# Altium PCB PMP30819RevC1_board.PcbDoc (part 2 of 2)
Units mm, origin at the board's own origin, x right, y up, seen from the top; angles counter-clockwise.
Board outline 73.66 x 66.04 mm, 4 copper layers (Top Layer, Layer 1, Layer 2, Bottom Layer), stack 1.787 mm thick; 100 components, 30 nets, 255 pads, 105 vias.
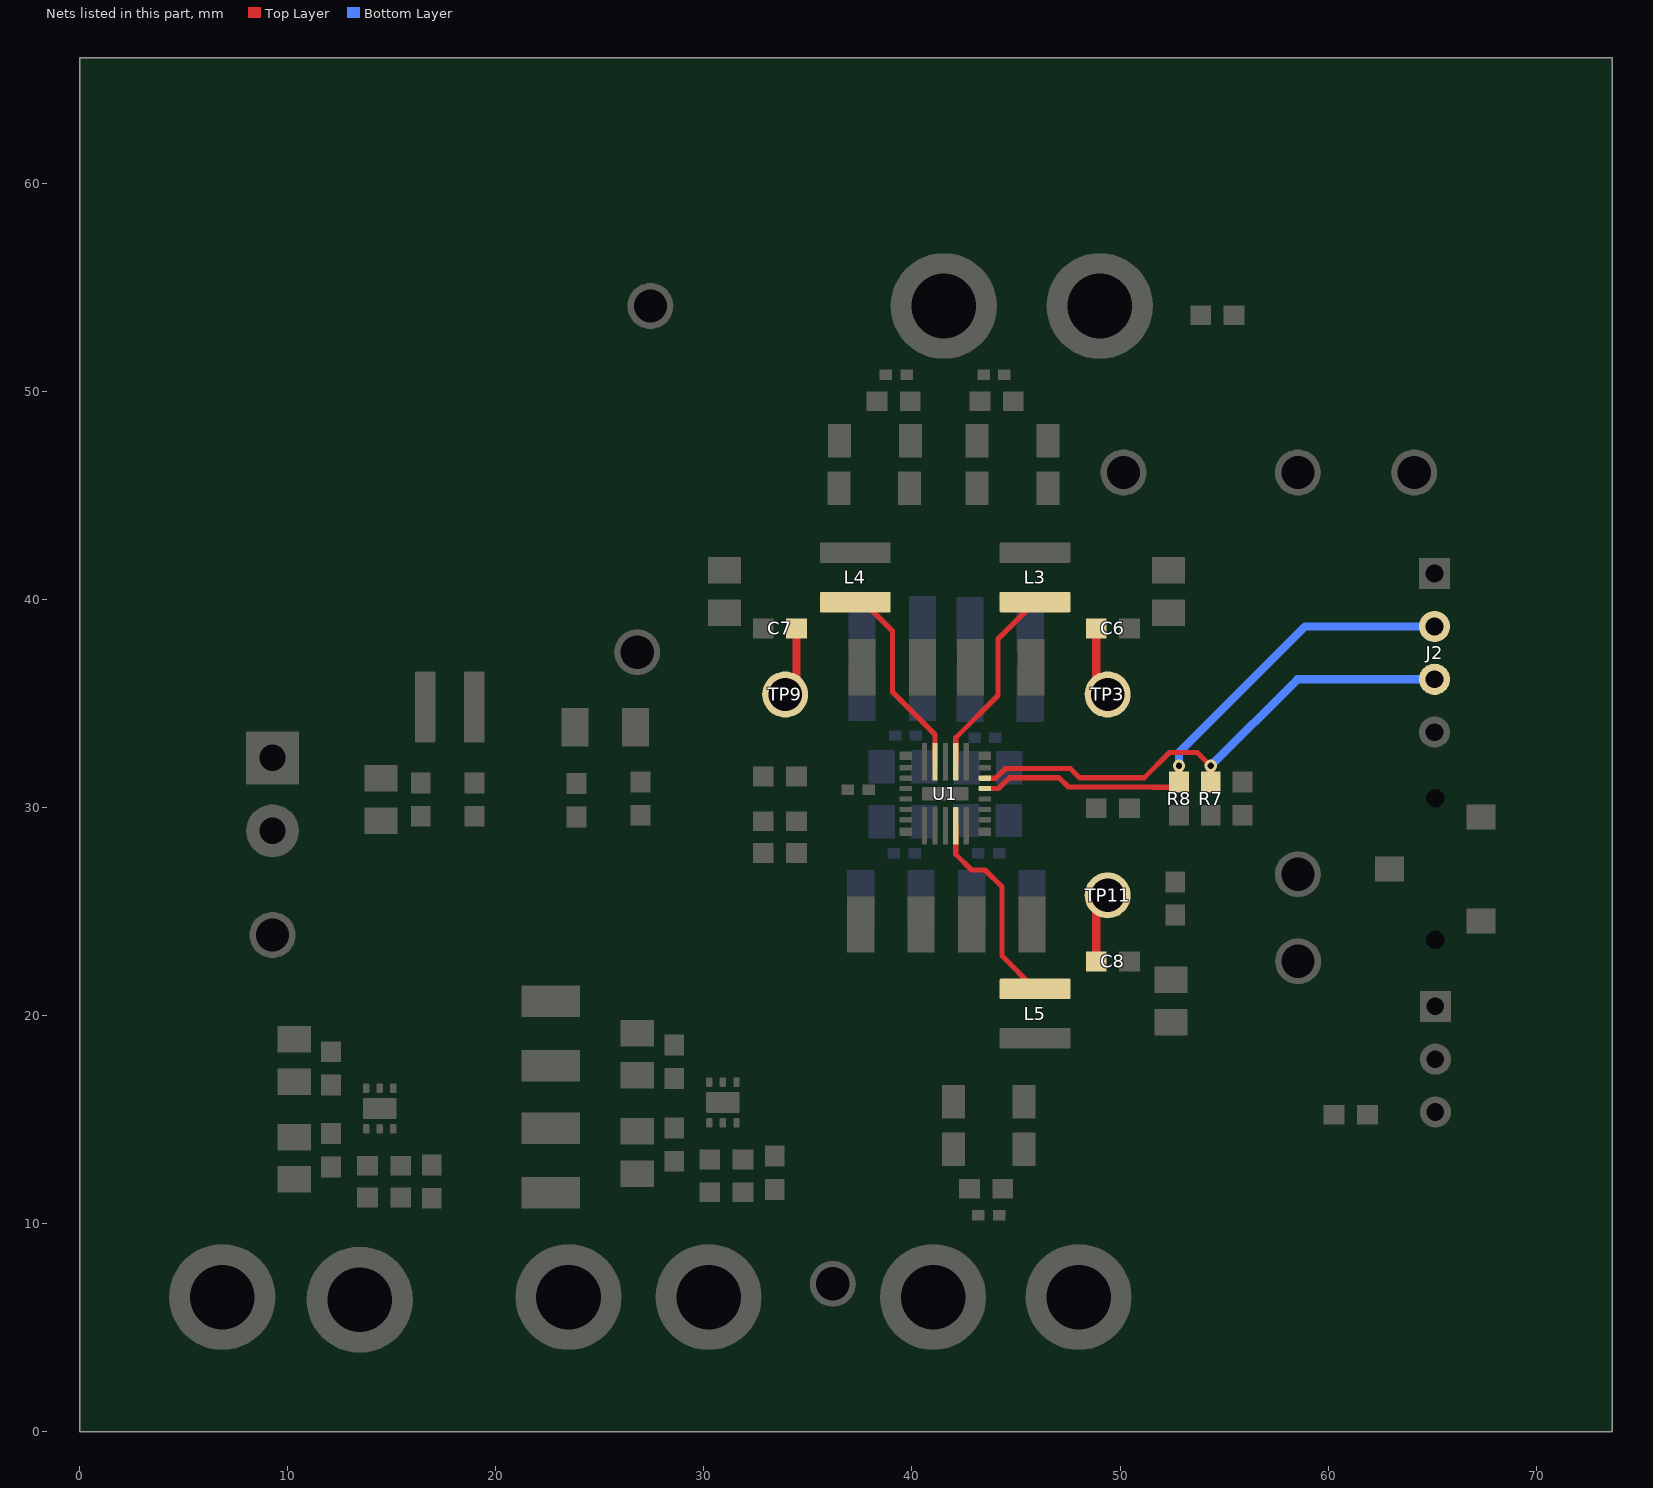
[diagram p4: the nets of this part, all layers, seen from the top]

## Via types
v1: diameter 0.6, hole 0.3, Top Layer to Bottom Layer, tented both sides, 66 vias
v2: diameter 0.7, hole 0.4, Top Layer to Bottom Layer, 20 vias
v3: diameter 0.6, hole 0.3, Top Layer to Bottom Layer, 11 vias
v4: diameter 0.9, hole 0.5, Top Layer to Bottom Layer, 6 vias
v5: diameter 0.9, hole 0.5, Top Layer to Bottom Layer, tented top, 1 vias
v6: diameter 0.7, hole 0.3, Top Layer to Bottom Layer, 1 vias

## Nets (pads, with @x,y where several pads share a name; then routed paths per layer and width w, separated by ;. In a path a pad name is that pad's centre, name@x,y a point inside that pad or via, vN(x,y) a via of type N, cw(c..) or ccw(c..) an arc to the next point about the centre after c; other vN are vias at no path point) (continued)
SCL: J2.2 R8.2 U1.5 | length 26
  Top Layer w0.25: U1.5@43.505,30.913 44.16,30.913 44.681,31.434 47.072,31.434 47.522,30.984 51.596,30.984 51.599,30.98 52.584,30.98 R8.2@52.832,31.228
  Top Layer w0.4: R8.2@52.832,31.228 v1(52.832,32.004)
  Bottom Layer w0.4: v1(52.832,32.004) 52.832,32.647 58.889,38.704 J2.2@65.113,38.704
SDA: J2.3 R7.2 U1.6 | length 25.3
  Top Layer w0.25: U1.6@43.505,31.413 44.024,31.413 44.495,31.884 47.259,31.884 47.265,31.877 47.607,31.877 48.051,31.434 51.158,31.434 52.376,32.651 53.709,32.651 v1(54.356,32.004)
  Top Layer w0.4: R7.2@54.356,31.228 v1(54.356,32.004)
  Bottom Layer w0.4: v1(54.356,32.004) 58.516,36.164 J2.3@65.113,36.164
SW_0: C6.1 L3.1 TP3.1 U1.10 | length 12.6
  Top Layer w0.25: U1.10@42.105,32.203 42.105,33.358 44.137,35.39 44.137,38.095 L3.1@45.915,39.873
  Top Layer w0.4: C6.1@48.857,38.608 48.857,35.979 TP3.1@49.403,35.433
SW_1: C7.1 L4.1 TP9.1 U1.12 | length 12.9
  Top Layer w0.25: L4.1@37.279,39.873 37.676,39.873 39.057,38.492 39.057,35.552 41.105,33.504 U1.12@41.105,32.203
  Top Layer w0.4: TP9.1@33.909,35.433 34.455,35.979 C7.1@34.455,38.608
SW_2: C8.1 L5.1 TP11.1 U1.25 | length 13.2
  Top Layer w0.25: U1.25@42.105,29.123 42.105,27.754 42.855,27.004 43.516,27.004 44.323,26.197 44.323,22.88 L5.1@45.915,21.288
  Top Layer w0.4: C8.1@48.857,22.606 48.857,25.235 TP11.1@49.403,25.781
pads on no net: S1.MH1 S1.MH2 U1. U1.23 U2.5 U2.7@13.973,15.537 U2.7@14.873,15.537 U12.5 U12.7@30.463,15.823 U12.7@31.363,15.823

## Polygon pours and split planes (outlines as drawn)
3V3 on Top Layer "TOP_LAYER_3V3_P000" (solid, remove dead copper, pour order 0): 23.989,10.776 20.683,10.776 20.263,11.196 20.263,11.75 20.739,12.227 23.989,12.227
GND on Top Layer "TOP_LAYER_GND_P152" (solid, remove dead copper, pour order 152): 2.286,23.876 31.936,23.876 38.645,17.167 38.645,5.014 41.119,2.54 59.711,2.54 59.711,63.5 2.54,63.5
3V3 on Top Layer "TOP_LAYER_3V3_P002" (solid, remove dead copper, pour order 2): 9.586,18.255 11.099,18.255 11.614,17.74 12.62,17.74 13.453,16.907 14.092,16.907 14.092,19.287 12.739,20.639 9.586,20.639
NetC34_1 on Top Layer "TOP_LAYER_NETC34_1_P004" (solid, remove dead copper, pour order 4): 9.5,12.776 11.136,12.776 11.614,13.254 13.373,13.25 13.373,13.601 13.614,13.843 13.896,13.843 14.322,13.417 14.322,10.317 15.114,9.525 16.637,8.001 16.637,2.54 10.311,2.54 10.311,10.481 9.521,11.27
NetC137_1 on Top Layer "TOP_LAYER_NETC137_1_P006" (solid, remove dead copper, pour order 6): 21.234,19.955 24.356,19.955 25.788,18.523 27.674,18.523 28.107,18.09 29.412,18.09 29.821,17.681 30.181,17.681 30.181,18.46 28.616,20.025 26.687,20.025 25.258,21.454 21.234,21.454
NetC134_1 on Top Layer "TOP_LAYER_NETC134_1_P012" (solid, remove dead copper, pour order 12): 30.003,14.001 29.562,13.56 29.382,13.56 29.307,13.485 27.958,13.485 27.529,13.056 26.01,13.056 26.01,11.666 26.372,11.303 26.372,10.218 27.608,8.983 27.608,2.573 32.732,2.573 32.732,7.9 30.813,9.819 30.813,13.655 30.462,14.005
GND on Top Layer "TOP_LAYER_GND_P150" (solid, remove dead copper, pour order 150): 17.4,8.08 14.579,10.9 9.573,10.9 9.573,2.54 2.466,2.54 2.466,23.013 26.233,23.013 37.421,23.013 39.535,20.899 39.559,9.525 26.338,9.525 26.338,2.54 17.4,2.54
GND on Top Layer "TOP_LAYER_GND_P144" (solid, remove dead copper, pour order 144): 43.472,21.717 43.472,20.282 44.069,19.685 43.479,19.095 43.479,5.358 41.989,3.867 40.172,3.867 38.481,5.559 38.481,22.208 40.022,23.749 42.623,23.749
NetC7_2 on Top Layer "TOP_LAYER_NETC7_2_P142" (solid, remove dead copper, pour order 142): 33.401,37.922 33.06,37.581 31.133,37.581 30.207,38.506 30.207,40.065 30.263,40.121 32.904,40.121 33.401,39.624
GND on Top Layer "TOP_LAYER_GND_P138" (solid, remove dead copper, pour order 138): 39.851,40.001 39.212,40.64 33.819,40.64 33.589,40.41 30.456,40.41 30.099,40.767 30.099,42.36 30.263,42.524 32.185,42.524 33.18,41.529 39.274,41.529 39.861,42.116
GND on Top Layer "TOP_LAYER_GND_P132" (solid, remove dead copper, pour order 132): 43.18,41.529 50.686,41.529 51.956,42.799 55.35,42.799 55.584,42.565 55.584,41.058 55.165,40.638 43.931,40.638 43.415,40.121 43.035,40.121
NetC6_2 on Top Layer "TOP_LAYER_NETC6_2_P126" (solid, remove dead copper, pour order 126): 49.936,39.333 50.679,40.076 53.049,40.076 53.34,39.785 53.34,37.867 52.768,37.295 50.317,37.295 49.936,37.676
NetC8_2 on Top Layer "TOP_LAYER_NETC8_2_P122" (solid, remove dead copper, pour order 122): 53.467,20.959 50.49,20.959 49.94,21.509 49.94,23.106 50.165,23.331 53.193,23.331 53.631,22.893 53.631,21.063 53.467,20.899
GND on Top Layer "TOP_LAYER_GND_P120" (solid, remove dead copper, pour order 120): 43.481,23.341 43.481,21.103 44.137,20.447 53.176,20.447 53.467,20.156 53.467,18.791 53.26,18.584 50.487,18.584 49.385,19.685 40.411,19.685 39.756,20.34 39.756,26.161 41.127,27.532 41.127,27.772 41.384,28.028 41.605,28.028 41.783,27.851 41.783,26.645 42.545,25.883 43.332,25.883 43.485,25.73
GND on Top Layer "TOP_LAYER_GND_P116" (solid, remove dead copper, pour order 116): 71.12,63.5 61.341,63.5 61.341,2.54 71.12,2.54
GND on Top Layer "TOP_LAYER_GND_P114" (solid, remove dead copper, pour order 114): 7.747,30.099 27.413,30.099 27.413,23.876 7.747,23.876
3V3 on Top Layer "TOP_LAYER_3V3_P112" (solid, remove dead copper, pour order 112): 49.107,19.431 44.207,19.431 43.815,19.039 43.815,9.157 46.495,6.477 48.26,6.477 49.107,7.324
5VS on Top Layer "TOP_LAYER_5VS_P108" (solid, remove dead copper, pour order 108): 29.464,49.27 29.464,49.216 29.972,48.708 29.972,42.816 29.781,42.625 29.781,38.257 31.563,36.475 31.563,23.876 28.107,23.876 28.107,30.48 26.037,30.48 26.036,30.663 26.036,47.565 27.74,49.27
NetC3_1 on Top Layer "TOP_LAYER_NETC3_1_P106" (solid, remove dead copper, pour order 106): 18.415,30.663 24.511,30.663 24.511,36.576 18.415,36.576
NetC1_1 on Top Layer "TOP_LAYER_NETC1_1_P104" (solid, remove dead copper, pour order 104): 7.747,30.734 17.116,30.734 17.116,36.576 7.747,36.576
1VD1 on Top Layer "TOP_LAYER_1VD1_P094" (solid, remove dead copper, pour order 94): 39.111,55.819 40.315,57.023 42.845,57.023 44.188,55.68 44.188,41.758 50.433,41.758 52.451,43.776 52.451,56.388 47.625,61.214 35.306,61.214 31.518,57.426 31.518,43.205 32.965,41.758 38.989,41.758 38.989,50.038 39.111,50.16
GND on Top Layer "TOP_LAYER_GND_P092" (solid, remove dead copper, pour order 92): 43.848,41.041 43.848,54.565 43.034,55.379 39.943,55.379 39.37,54.806 39.37,41.021
5VS on Top Layer "TOP_LAYER_5VS_P082" (solid, remove dead copper, pour order 82): 36.656,22.784 36.085,23.341 36.085,27.055 36.97,27.94 40.386,27.94 40.513,28.067 40.605,28.113 40.757,27.961 40.757,27.504 39.438,26.185 39.438,23.899 38.324,22.784
SW_2 on Top Layer "TOP_LAYER_SW_2_P080" (solid, remove dead copper, pour order 80): 42.123,26.647 cw(c42.462,26.987) 41.982,26.987 41.973,27.088 41.973,27.819 41.992,27.837 42.528,27.444 ccw(c43.171,28.087) 43.171,27.178 44.27,27.178 cw(c44.27,26.745) 44.577,27.051 44.608,27.02 cw(c44.091,26.483) 44.836,26.497 44.836,22.987 ccw(c45.17,22.98) 44.93,22.749 45.206,22.473 ccw(c45.747,23.029) 45.758,22.253 47.348,22.253 ccw(c47.348,22.784) 47.879,22.784 cw(c48.426,22.784) 48.426,23.331 49.187,23.331 cw(c49.188,22.934) 49.584,22.934 49.584,20.898 cw(c49.489,20.898) 49.489,20.803 48.978,20.803 44.45,20.803 44.094,20.803 cw(c44.094,21.082) 43.815,21.082 43.815,25.809 ccw(c43.427,25.809) 43.736,26.043 ccw(c43.364,25.671) 43.364,26.197 43.08,26.197 42.997,26.197 cw(c42.997,27.221) 42.273,26.497
5VS on Top Layer "TOP_LAYER_5VS_P062" (solid, remove dead copper, pour order 62): 42.926,27.94 46.183,27.94 47.072,27.051 47.072,23.183 46.673,22.784 45.288,22.784 45.083,22.989 45.083,26.968 44.588,27.463 43.488,27.463 43.138,27.813
5VS on Top Layer "TOP_LAYER_5VS_P058" (solid, remove dead copper, pour order 58): 45.036,38.09 46.822,38.09 47.312,37.6 47.312,34.203 46.319,33.21 43.737,33.21 43.63,33.317 45.036,34.724
5VS on Top Layer "TOP_LAYER_5VS_P050" (solid, remove dead copper, pour order 50): 39.705,33.363 37.085,33.363 36.095,34.352 36.095,37.478 36.754,38.137 38.295,38.137 38.295,35.078 39.692,33.681 39.692,33.565
SW_1 on Top Layer "TOP_LAYER_SW_1_P044" (solid, remove dead copper, pour order 44): 39.756,35.026 cw(c40.571,35.841) 39.418,35.841 39.429,35.902 39.429,39.826 ccw(c39.14,39.826) 39.345,40.03 39.08,40.295 ccw(c38.894,40.108) 38.894,40.372 34.7,40.372 ccw(c34.698,39.539) 33.865,39.54 33.865,38.308 ccw(c34.29,38.308) 34.29,37.883 35.244,37.883 ccw(c35.244,38.133) 35.42,37.956 cw(c36.347,37.03) 36.347,38.34 38.343,38.34 cw(c38.343,38.126) 38.557,38.126 38.557,35.548 ccw(c39.491,35.595) 38.864,34.901 40.017,33.748 40.861,33.748 41.015,33.87 40.911,33.87
GND on Top Layer "TOP_LAYER_GND_P042" (solid, remove dead copper, pour order 42): 43.848,40.515 43.848,41.566 39.355,41.566 39.355,40.379 39.819,39.915 39.819,35.406 41.127,34.098 41.884,34.098 41.884,34.12 42.03,34.12 43.434,35.524 43.434,40.101
SW_0 on Top Layer "TOP_LAYER_SW_0_P026" (solid, remove dead copper, pour order 26): 44.65,35.245 cw(c43.695,35.203) 44.401,34.558 43.724,33.881 cw(c43.485,34.12) 43.485,33.782 43.115,33.782 ccw(c43.115,32.834) 42.445,33.504 41.884,33.504 41.884,33.546 43.04,34.702 43.146,34.82 cw(c43.313,34.653) 43.313,34.889 ccw(c43.313,35.271) 43.583,35.001 43.718,35.136 ccw(c43.485,35.369) 43.815,35.369 43.815,40.048 cw(c44.103,40.048) 43.899,40.252 cw(c44.234,39.845) 44.234,40.372 48.856,40.372 cw(c48.856,39.801) 49.427,39.801 49.427,38.133 cw(c49.177,38.133) 49.177,37.883 48.605,37.883 cw(c48.605,38.227) 48.26,38.227 48.26,38.339 ccw(c48.073,38.339) 48.073,38.526 44.958,38.526 ccw(c44.958,38.233) 44.75,38.44 ccw(c45.004,38.187) 44.645,38.186 44.65,38.09
GND on Bottom Layer "BOTTOM_LAYER_GND_P098" (solid, remove dead copper, pour order 98): 71.12,2.54 71.12,63.5 2.54,63.5 2.54,2.54
5VS on Bottom Layer "BOTTOM_LAYER_5VS_P090" (solid, remove dead copper, pour order 90): 28.067,23.622 33.43,18.259 36.355,18.259 37.074,18.977 37.074,29.038 28.067,29.038
5VS on Bottom Layer "BOTTOM_LAYER_5VS_P086" (solid, remove dead copper, pour order 86): 26.036,40.076 32.206,40.076 36.085,43.955 36.085,47.401 34.255,49.231 27.702,49.231 26.036,47.565
5VS on Bottom Layer "BOTTOM_LAYER_5VS_P068" (solid, remove dead copper, pour order 68): 47.677,32.824 47.677,35.828 48.081,36.232 49.188,36.232 49.187,46.888 46.859,49.216 33.983,49.216 31.757,46.99 31.757,36.576 32.265,36.068 35.052,36.068 35.453,35.667 35.393,32.94 37.181,31.152 39.188,31.152 39.559,31.523 39.559,39.671 38.915,40.314 38.915,41.906 39.192,42.183 43.788,42.183 44.234,41.737 44.234,40.638 43.815,40.237 43.815,33.157 44.433,32.54 45.912,31.06
5VS on Bottom Layer "BOTTOM_LAYER_5VS_P066" (solid, remove dead copper, pour order 66): 47.677,27.929 47.677,25.258 48.051,24.884 49.149,24.884 49.149,18.706 47.677,17.234 34.445,17.234 31.8,19.879 31.8,23.959 36.382,28.541 38.896,28.541 39.37,28.067 39.37,22.823 39.645,22.548 43.587,22.548 43.801,22.762 43.801,28.436 47.117,28.489
5VS on Bottom Layer "BOTTOM_LAYER_5VS_P048" (solid, remove dead copper, pour order 48): 36.643,22.784 36.085,23.341 36.085,28.338 37.846,30.099 39.497,30.099 39.497,27.355 39.438,27.296 39.438,23.899 38.324,22.784
5VS on Bottom Layer "BOTTOM_LAYER_5VS_P046" (solid, remove dead copper, pour order 46): 43.861,30.226 45.974,30.226 47.117,29.083 47.117,23.228 46.673,22.784 45.288,22.784 45.083,22.989 45.083,26.655 44.484,27.254 44.297,27.254 43.861,27.69
GND on Bottom Layer "BOTTOM_LAYER_GND_P040" (solid, remove dead copper, pour order 40): 43.405,31.063 43.405,28.284 43.527,28.163 43.527,24.084 43.497,24.054 43.497,23.063 39.83,23.063 39.83,31.24
GND on Bottom Layer "BOTTOM_LAYER_GND_P024" (solid, remove dead copper, pour order 24): 43.375,30.263 43.375,34.065 43.43,34.12 43.43,40.137 43.931,40.638 43.931,41.566 39.25,41.566 39.25,40.484 39.819,39.915 39.819,30.263
5VS on Bottom Layer "BOTTOM_LAYER_5VS_P010" (solid, remove dead copper, pour order 10): 45.064,40.122 46.651,40.122 47.312,39.461 47.312,32.46 45.877,31.025 43.976,31.025 43.976,32.638 43.685,32.929 43.655,32.929 43.655,33.654 45.064,35.063
5VS on Bottom Layer "BOTTOM_LAYER_5VS_P008" (solid, remove dead copper, pour order 8): 39.188,32.651 39.559,33.022 39.559,33.779 39.409,33.929 39.409,34.027 38.299,35.137 38.299,40.181 36.428,40.181 36.099,39.852 36.099,32.234 37.181,31.152 39.188,31.152
GND on Layer 2 "LAYER_2_GND_P148" (solid, remove dead copper, pour order 148): 2.54,2.54 2.54,63.5 71.12,63.5 71.12,2.54
3V3 on Layer 2 "LAYER_2_3V3_P130" (solid, remove dead copper, pour order 130): 51.167,3.664 47.271,3.664 39.976,10.959 20.634,10.959 12.575,19.018 9.295,19.018 9.295,20.932 9.699,21.336 15,21.336 22.536,13.8 44.604,13.8 52.107,6.297 52.107,5.2
GND on Layer 1 "LAYER_1_GND_P146" (solid, remove dead copper, pour order 146): 71.12,2.54 71.12,63.5 2.54,63.5 2.54,2.54

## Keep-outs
Keep-Out Layer:
  text ".Layer_Name" at 14.656,-21.806 h1.52

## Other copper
Top Layer:
  pour cut-out: 8.073,23.174 8.128,22.871 8.52,22.479 8.647,22.352 9.751,22.352 9.878,22.479 10.343,22.943 10.343,23.114
  pour cut-out: 34.925,33.782 36.327,33.782 36.981,33.128 39.99,33.128 40.005,33.113 40.005,32.463 39.8,32.258 34.925,32.258
  text ".Layer_Name" at 14.656,-21.806 h1.52
Layer 1:
  pour cut-out: 44.069,21.844 44.069,20.701 47.752,20.701 47.752,21.844
  pour cut-out: 44.069,40.513 44.069,39.243 47.752,39.243 47.752,40.513
  pour cut-out: 35.433,40.513 35.433,39.114 39.116,39.114 39.116,40.513
  pour cut-out: 35.952,32.564 35.952,33.508 34.945,33.508 34.945,32.564
Layer 2:
  pour cut-out: 35.952,32.564 35.952,33.508 34.945,33.508 34.945,32.564
Bottom Layer:
  pour cut-out: 35.448,32.564 35.448,33.508 34.945,33.508 34.945,32.564
  text ".Layer_Name" at 14.656,-21.806 h1.52

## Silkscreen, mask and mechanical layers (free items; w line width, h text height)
Top Overlay:
  text "GND" at 40.124,57.426 h1
  text "1.1V" at 47.745,57.426 h1
  text "NWA" at 57.176,48.575 h1
  text "AGND" at 62.569,48.574 h1
  text "VIN" at 4.191,31.981 h1 r90
  text "GND" at 4.191,27.135 h1 r90
  text "NWA" at 56.475,24.689 h1 r90
  text "3v3" at 56.463,19.955 h1 r90
  text "'.PRJ_Number'.PCB_Rev" at 52.557,3.048 h2
  text "GND" at 5.461,2.032 h1
  text "2.5V" at 12.065,2.032 h1
  text "GND" at 21.869,2.032 h1
  text "1.1V" at 28.991,2.032 h1
  text "GND" at 39.83,2.032 h1
  text "3.3V" at 46.792,2.032 h1
  text ".Layer_Name" at 14.656,-21.806 h1.52
Bottom Overlay:
  text ".Layer_Name" at 14.656,-21.806 h1.52
Top Paste:
  text ".Layer_Name" at 14.656,-21.806 h1.52
Bottom Paste:
  text ".Layer_Name" at 14.656,-21.806 h1.52
Top Solder:
  text ".Layer_Name" at 14.656,-21.806 h1.52
  text ".Layer_Name" at 14.656,-21.806 h1.52
Bottom Solder:
  text "'.PRJ_Number'.PCB_Rev" at 70.358,3.529 h2
  text ".Layer_Name" at 14.656,-21.806 h1.52
Drill Guide:
  text ".Layer_Name" at 14.656,-21.806 h1.52
M1 Board Outline:
  the board outline again, w0.254
  text ".Layer_Name" at 14.656,-21.806 h1.52
M2 Board Dimensions:
  rectangle: 0,-6.985 3.175,-3.81
  rectangle: 3.175,-10.16 12.7,-6.985
  lines w0.178: 0,-6.985 25.4,-6.985 ; 3.175,-10.16 3.175,-3.81 ; 6.35,-10.16 6.35,-3.81 ; 12.7,-10.16 12.7,-3.81 ; 19.05,-10.16 19.05,-3.81 ; 0,-10.16 25.4,-10.16 25.4,-3.81 0,-3.81 0,-10.16
  text "'.Print_Date' '.Print_Time'" at 0.381,67.183 h1.5
  text ".Layer_Name" at 14.656,-21.806 h1.52
M3 3D STEP Top:
  text ".Layer_Name" at 14.656,-21.806 h1.52
M4 3D STEP Bottom:
  text ".Layer_Name" at 14.656,-21.806 h1.52
M5 Assembly Top:
  lines w0.254: -7.417,-23.626 160.223,-23.626 ; -7.417,-18.462 160.274,-18.462 ; -7.417,-13.297 -7.417,-28.791 94.31,-28.791 160.274,-28.791 160.274,-13.297 -7.404,-13.297 -7.404,-28.791 32.614,-28.791 ; 55.194,-28.791 55.194,-13.297 ; 87.376,-18.462 87.376,-13.297 ; 108.712,-18.462 108.712,-13.297 ; 124.511,-28.956 124.511,-23.804
  text "COMPONENTS MARKED 'DNP' SHOULD NOT BE POPULATED." at 29.299,-8.09 h1.52
  text "ASSEMBLY VARIANT:" at 29.286,-11.024 h1.52
  text ".VariantName" at 55.601,-11.024 h1.52
  text "PCB VIEWED FROM TOP SIDE" at -5.804,-16.654 h1.52
  text "BOARD #:" at 57.099,-16.654 h1.52
  text ".PRJ_Number" at 70.955,-16.654 h1.52
  text "REV:" at 92.405,-16.654 h1.52
  text ".PCB_Rev" at 99.809,-16.654 h1.52
  text "SVN REV:" at 113.69,-16.654 h1.52
  text ".VersionControl_RevNumber" at 126.543,-16.654 h1.52
  text "TID #:" at 57.099,-21.819 h1.52
  text ".TID" at 70.955,-21.819 h1.52
  text "PLOT NAME =" at -5.804,-27.034 h1.52
  text ".plot_File_Name" at 14.656,-27.034 h1.52
  text "GENERATED    :" at 57.15,-27.034 h1.52
  text ".Print_Date" at 79.235,-27.034 h1.52
  text ".Print_Time" at 97.752,-27.034 h1.52
  text "TEXAS INSTRUMENTS" at 129.87,-27.034 h1.52
M6 Assembly Bottom:
  lines w0.254: -7.429,-18.474 160.261,-18.474 ; -7.379,-23.639 160.261,-23.639 ; 28.334,-28.969 28.334,-23.817 ; 44.133,-18.474 44.133,-13.31 ; 65.468,-18.474 65.468,-13.31 ; 97.65,-28.804 97.65,-13.31 ; 120.231,-28.804 160.249,-28.804 160.249,-13.31 -7.429,-13.31 -7.429,-28.804 58.534,-28.804 160.261,-28.804 160.261,-13.31
  text "COMPONENTS MARKED 'DNP' SHOULD NOT BE POPULATED." at 154.991,-8.077 h1.52
  text ".VariantName" at 128.473,-11.024 h1.52
  text "ASSEMBLY VARIANT:" at 154.864,-11.024 h1.52
  text ".VersionControl_RevNumber" at 26.302,-16.667 h1.52
  text "SVN REV:" at 39.154,-16.667 h1.52
  text ".PCB_Rev" at 53.035,-16.667 h1.52
  text "REV:" at 60.439,-16.667 h1.52
  text ".PRJ_Number" at 81.89,-16.667 h1.52
  text "BOARD #:" at 95.745,-16.667 h1.52
  text "PCB VIEWED FROM BOTTOM SIDE" at 158.648,-16.667 h1.52
  text ".TID" at 81.89,-21.831 h1.52
  text "TID #:" at 95.745,-21.831 h1.52
  text "TEXAS INSTRUMENTS" at 22.974,-27.047 h1.52
  text ".Print_Time" at 55.093,-27.047 h1.52
  text ".Print_Date" at 73.609,-27.047 h1.52
  text "GENERATED    :" at 95.694,-27.047 h1.52
  text ".plot_File_Name" at 138.189,-27.047 h1.52
  text "PLOT NAME =" at 158.648,-27.047 h1.52
M9 Title Sheet:
  drawing of 57 lines, arcs and shapes, not listed
  text "1" at 18.792,204.127 h1.78
  text "2" at 82.182,204.127 h1.78
  text "3" at 145.411,204.127 h1.78
  text "4" at 209.08,204.127 h1.78
  text "5" at 272.555,204.127 h1.78
  text "6" at 336.182,204.127 h1.78
  text "A" at -10.579,175.095 h1.78
  text "A" at 365.341,175.095 h1.78
  text "B" at -10.579,114.643 h1.78
  text "B" at 365.341,114.643 h1.78
  text "C" at -10.579,54.318 h1.78
  text "C" at 365.341,54.318 h1.78
  text "PROJECT TITLE:" at 288.125,7.048 h1.14
  text ".PRJ_Title" at 289.395,3.662 h1.78
  text "DESIGNED FOR:" at 288.125,-0.597 h1.14
  text ".PRJ_Customer" at 289.395,-4.153 h1.78
  text "D" at -10.579,-5.88 h1.78
  text "D" at 365.341,-5.88 h1.78
  text "FILE NAME:" at 288.125,-8.217 h1.14
  text ".PCB_File_Name_No_Path" at 289.395,-11.265 h1.78
  text "Texas Instruments (TI) and/or its licensors do not warrant the accuracy or completeness of this specification" at 161.9,-15.376 h1.14
  text "ENGINEER:" at 288.125,-15.583 h1.14
  text "LAYOUT BY:" at 326.352,-15.583 h1.14
  text "or any information contained therein. TI and/or its licensors do not warrant that this design will meet" at 160.757,-18.237 h1.14
  text ".PRJ_Engineer" at 289.395,-19.52 h1.78
  text ".PCB_Layout" at 327.635,-19.52 h1.78
  text "the specifications, will be suitable for your application or fit for any particular purpose, or will operate in" at 160.757,-21.099 h1.14
  text ".Layer_Name" at 14.656,-21.806 h1.52
  text "ALTIUM DESIGNER VERSION:" at 326.352,-23.457 h1.14
  text "an implementation. TI and/or its licensors do not warrant that the design is production worthy. You should" at 160.757,-23.961 h1.14
  text "completely validate and test your design implementation to confirm the system functionality for your application." at 161.9,-26.822 h1.14
  text ".print_Scale" at 289.395,-26.843 h1.78
  text ".Application_BuildNumber" at 327.635,-26.843 h1.78
  text "1" at 18.792,-32.093 h1.78
  text "2" at 82.182,-32.093 h1.78
  text "3" at 145.411,-32.093 h1.78
  text "4" at 209.08,-32.093 h1.78
  text "5" at 272.555,-32.093 h1.78
  text "6" at 336.182,-32.093 h1.78
M10 Fab Notes:
  drawing of 189 lines, arcs and shapes, not listed
  text "DESIGN INFORMATION" at 314.503,161.447 h1.52
  text "MIN. TRACK WIDTH:" at 298.131,158.091 h1.52
  text "8" at 325.976,158.091 h1.52
  text "MIL" at 329.907,158.091 h1.52
  text "MIN. CLEARANCE:" at 298.131,154.938 h1.52
  text "0.2" at 324.452,154.938 h1.52
  text "mm" at 329.907,154.938 h1.52
  text "MIN. VIA PAD SIZE:" at 298.131,151.785 h1.52
  text "24" at 325.214,151.785 h1.52
  text "MIL" at 329.907,151.785 h1.52
  text "0.05mm (2MIL)" at 315.784,148.486 h1.52
  text "MINIMUM ANNULAR RING" at 289.769,148.277 h1.52
  text "EXTERNAL" at 333.768,148.277 h1.52
  text "PER" at 294.849,145.48 h1.52
  text "IPC-D-275 CLASS 2 LEVEL C" at 300.437,145.48 h1.52
  text "MIL, HOLES" at 338.238,142.928 h1.52
  text "+/-" at 328.27,142.709 h1.52
  text "+/-" at 349.961,142.709 h1.52
  text "REGISTRATION TOLERANCES:" at 289.769,142.682 h1.52
  text "METAL" at 320.243,142.682 h1.52
  text "5" at 334.879,142.683 h1.52
  text "3" at 356.037,142.683 h1.52
  text "MIL" at 358.99,142.682 h1.52
  text "HOLE SIZE TOLERANCE (UNLESS OTHERWISE SPECIFIED):" at 289.769,140.185 h1.52
  text "+/-" at 349.961,140.112 h1.52
  text "3" at 356.037,140.085 h1.52
  text "MIL" at 358.99,140.085 h1.52
  text "MATERIAL:" at 287.87,136.589 h1.52
  text "FR-4 High Tg" at 312.926,133.324 h1.52
  text "X" at 309.257,133.122 h1.52
  text "FR-408" at 298.563,133.007 h1.52
  text "OTHER" at 336.358,133.007 h1.52
  text "62 MIL (1.6mm) +/-10%" at 306.694,129.374 h1.52
  text "X" at 303.643,129.312 h1.52
  text "THICKNESS:" at 289.769,129.165 h1.52
  text "OTHER" at 339.33,129.165 h1.52
  text "TOLERANCE:" at 289.769,125.652 h1.52
  text "X" at 311.314,125.652 h1.52
  text "ANSI IPC-6012 TYPE 3 CLASS 2" at 315.836,125.652 h1.52
  text "OTHER +/-" at 315.835,121.989 h1.52
  text "BOW & TWIST:" at 289.769,118.302 h1.52
  text "X" at 311.314,118.302 h1.52
  text "ANSI IPC-6012 TYPE 3 CLASS 2" at 315.836,118.302 h1.52
  text "OTHER +/-" at 315.835,114.576 h1.52
  text "DRILLING:" at 287.87,111.258 h1.52
  text "NC_DRILL FILES" at 332.599,108.586 h1.52
  text "REFERENCE:" at 289.769,108.486 h1.52
  text "X" at 306.463,108.484 h1.52
  text "AS SHOWN" at 310.984,108.486 h1.52
  text "X" at 329.348,108.486 h1.52
  text "OTHER" at 340.168,104.873 h1.52
  text "PTH COPPER THICKNESS:" at 289.761,104.783 h1.52
  text "X" at 318.697,104.783 h1.52
  text "20-30 um" at 321.948,104.783 h1.52
  text "BOARD FINISH:" at 287.87,101.034 h1.52
  text "SILKSCREEN:" at 291.812,98.237 h1.52
  text "X" at 316.14,98.237 h1.52
  text "TOP" at 319.112,98.237 h1.52
  text "X" at 329.094,98.237 h1.52
  text "BOTTOM" at 332.091,98.237 h1.52
  text "SILKSCREEN COLOR:" at 291.812,94.295 h1.52
  text "X" at 316.115,94.295 h1.52
  text "WHITE" at 319.112,94.295 h1.52
  text "OTHER" at 332.091,94.295 h1.52
  text "X" at 319.442,90.652 h1.52
  text "GREEN" at 322.439,90.652 h1.52
  text "OTHER" at 338.136,90.652 h1.52
  text "SOLDER RESIST COLOR:" at 291.812,90.477 h1.52
  text "X" at 319.442,86.734 h1.52
  text "MATTE" at 322.439,86.734 h1.52
  text "SEMI-GLOSS" at 338.125,86.717 h1.52
  text "IMMERSION GOLD (ENIG)" at 314.819,82.345 h1.52
  text "ENEPIG" at 348.793,82.162 h1.52
  text "SURFACE FINISH:" at 287.87,82.136 h1.52
  text "X" at 310.298,82.136 h1.52
  text "IMM. TIN/SILVER OR EQUIV" at 296.24,78.649 h1.52
  text "OTHER" at 332.599,78.549 h1.52
  text "ARRAY/PANEL:" at 287.87,74.602 h1.52
  text "CUT AND TRIM PER M1 BOARD OUTLINE" at 314.819,74.393 h1.52
  text "N.C. ROUTE" at 314.819,70.94 h1.52
  text "X" at 332.295,70.94 h1.52
  text "V. SCORE" at 336.816,70.94 h1.52
  text "CERTIFICATION:" at 287.87,67.66 h1.52
  text "MATERIALS AND WORKMANSHIP FOR ALL PCBS" at 306.285,67.66 h1.52
  text "TO MEET OR EXCEED THE REQUIREMENTS OF:" at 306.285,65.271 h1.52
  text "X" at 297.078,62.003 h1.52
  text "ANSI IPC-A-600F CLASS ->" at 300.329,62.003 h1.52
  text "X" at 342.188,62.003 h1.52
  text "2" at 344.982,62.003 h1.52
  text "1" at 336.981,61.965 h1.52
  text "3" at 353.973,61.965 h1.52
  text "X" at 317.702,58.252 h1.52
  text "RoHS" at 320.953,58.252 h1.52
  text "OTHER" at 337.321,58.252 h1.52
  text "PER ORDER" at 347.407,58.252 h1.52
  text "ALL BOARDS MUST MEET OR EXCEED UL94-V0 REQUIREMENTS." at 288.569,54.345 h1.52
  text "PCB MUST BEAR THE UL94V-0 UL REGISTERED MATERIAL ID NUMBER" at 288.569,51.397 h1.52
  text "ADDITIONAL REQUIREMENTS:" at 287.87,47.094 h1.52
  text "MICROSECTION:" at 289.769,44.373 h1.52
  text "YES" at 312.775,44.373 h1.52
  text "REQUIRED" at 334.657,40.707 h1.52
  text "BARE BOARD ELEC. TEST:" at 289.769,40.634 h1.52
  text "NONE" at 322.935,40.634 h1.52
  text "X" at 331.66,40.634 h1.52
  text "PER ORDER" at 349.693,40.634 h1.52
  text "XX MIL VIAS REQUIRE NON-CONDUCTIVE FILL AND PLANARIZE" at 294.04,35.428 h1.5
  text "XX MIL VIAS REQUIRE CONDUCTIVE FILL AND PLANARIZE" at 294.243,32.787 h1.52
  text "OUTER XX MIL TRACES REQUIRE 50 OHM SINGLE-ENDED IMPEDANCE" at 294.218,28.637 h1.47
  text "LAYER 2 & 3 (INNER LAYERS) XX MIL WIDE, XX MIL SPACE / TRACES REQUIRE 100 OHM DIFFERENTIAL IMPEDANCE" at 294.015,22.65 h1.52
  text ".Layer_Name" at 14.656,-21.806 h1.52
M11 Gerber Information:
  lines w0.254: -7.417,-23.626 160.223,-23.626 ; -7.417,-18.462 160.274,-18.462 ; -7.417,-13.297 -7.417,-28.791 94.31,-28.791 160.274,-28.791 160.274,-13.297 -7.404,-13.297 -7.404,-28.791 32.614,-28.791 ; 55.194,-28.791 55.194,-13.297 ; 87.376,-18.462 87.376,-13.297 ; 108.712,-18.462 108.712,-13.297 ; 124.511,-28.956 124.511,-23.804
  text "ALL ARTWORK VIEWED FROM TOP SIDE" at -5.804,-16.654 h1.52
  text "BOARD #:" at 57.099,-16.654 h1.52
  text ".PRJ_Number" at 70.955,-16.654 h1.52
  text "REV:" at 92.405,-16.654 h1.52
  text ".PCB_Rev" at 99.809,-16.654 h1.52
  text "SVN REV:" at 113.69,-16.654 h1.52
  text ".VersionControl_RevNumber" at 126.543,-16.654 h1.52
  text "LAYER NAME =" at -5.804,-21.806 h1.52
  text "TID #:" at 57.099,-21.819 h1.52
  text ".TID" at 70.955,-21.819 h1.52
  text "PLOT NAME =" at -5.804,-27.034 h1.52
  text ".plot_File_Name" at 14.656,-27.034 h1.52
  text "GENERATED    :" at 57.15,-27.034 h1.52
  text ".Print_Date" at 79.235,-27.034 h1.52
  text ".Print_Time" at 97.752,-27.034 h1.52
  text "TEXAS INSTRUMENTS" at 129.87,-27.034 h1.52
M12 Stackup:
  drawing of 295 lines, arcs and shapes, not listed
  text "Layer" at 249.119,181.737 h1.52
  text "Name" at 259.531,181.737 h1.52
  text "Material" at 283.147,181.737 h1.52
  text "Thickness" at 304.985,181.737 h1.52
  text "Constant" at 321.49,181.737 h1.52
  text "Board Layer Stack" at 335.965,181.737 h1.52
  text "Top Overlay" at 259.531,178.689 h1.52
  text "Top Solder" at 259.531,175.641 h1.52
  text "Solder Resist" at 283.147,175.641 h1.52
  text "0.40mil" at 304.985,175.641 h1.52
  text "3.5" at 321.49,175.641 h1.52
  text "1" at 249.119,172.593 h1.52
  text "Top Layer" at 259.531,172.593 h1.52
  text "1.40mil" at 304.985,172.593 h1.52
  text "Dielectric 1" at 259.531,169.545 h1.52
  text "PP-006" at 283.147,169.545 h1.52
  text "2.80mil" at 304.985,169.545 h1.52
  text "4.1" at 321.49,169.545 h1.52
  text "2" at 249.119,166.497 h1.52
  text "Layer 1" at 259.531,166.497 h1.52
  text "CF-004" at 283.147,166.497 h1.52
  text "1.38mil" at 304.985,166.497 h1.52
  text "Dielectric1" at 259.531,163.449 h1.52
  text "FR-4" at 283.147,163.449 h1.52
  text "59.20mil" at 304.985,163.449 h1.52
  text "4.8" at 321.49,163.449 h1.52
  text "3" at 249.119,160.401 h1.52
  text "Layer 2" at 259.531,160.401 h1.52
  text "CF-004" at 283.147,160.401 h1.52
  text "1.38mil" at 304.985,160.401 h1.52
  text "Dielectric 2" at 259.531,157.353 h1.52
  text "PP-006" at 283.147,157.353 h1.52
  text "2.80mil" at 304.985,157.353 h1.52
  text "4.1" at 321.49,157.353 h1.52
  text "4" at 249.119,154.305 h1.52
  text "Bottom Layer" at 259.531,154.305 h1.52
  text "1.40mil" at 304.985,154.305 h1.52
  text "Bottom Solder" at 259.531,151.257 h1.52
  text "Solder Resist" at 283.147,151.257 h1.52
  text "0.40mil" at 304.985,151.257 h1.52
  text "3.5" at 321.49,151.257 h1.52
  text "Bottom Overlay" at 259.531,148.209 h1.52
  text ".Layer_Name" at 14.656,-21.806 h1.52
M13 Component Bodies Top:
  text ".Layer_Name" at 14.656,-21.806 h1.52
M14 Component Bodies Bottom:
  text ".Layer_Name" at 14.656,-21.806 h1.52
M15 Courtyards Top:
  text ".Layer_Name" at 14.656,-21.806 h1.52
M16 Courtyards Bottom:
  text ".Layer_Name" at 14.656,-21.806 h1.52
Drill Drawing:
  circle w0.254: c136.241,71.717 r0.703
  lines w0.254: 135.538,66.095 136.944,66.095 136.241,64.69 135.538,66.095 ; 135.538,67.852 136.944,67.852 136.944,69.258 135.538,69.258 135.538,67.852 ; 135.538,74.528 135.89,74.528 136.241,74.177 136.593,74.528 136.944,74.528 136.593,74.88 136.944,75.231 136.593,75.231 136.241,75.582 135.89,75.231 135.538,75.231 135.89,74.88 135.538,74.528 ; 135.538,78.042 136.241,77.339 136.944,78.042 136.241,78.745 135.538,78.042 ; 135.538,80.853 135.89,80.853 135.89,80.501 136.593,80.501 136.593,80.853 136.944,80.853 136.944,81.556 136.593,81.556 136.593,81.907 135.89,81.907 135.89,81.556 135.538,81.556 135.538,80.853 ; 135.538,83.664 135.538,84.015 135.89,84.367 135.538,84.718 135.538,85.069 135.89,85.069 136.241,84.718 136.593,85.069 136.944,85.069 136.944,84.718 136.593,84.367 136.944,84.015 136.944,83.664 136.593,83.664 136.241,84.015 135.89,83.664 135.538,83.664 ; 135.538,86.826 136.241,87.177 136.944,86.826 136.593,87.529 136.944,88.232 136.241,87.88 135.538,88.232 135.89,87.529 135.538,86.826
  lines w0.305: 134.264,63.741 216.362,63.741 ; 134.264,89.04 216.362,89.04 ; 142.85,60.579 142.85,92.202 ; 151.287,60.579 151.287,92.202 ; 167.453,60.579 167.453,92.202 ; 174.037,60.579 174.037,92.202 ; 183.568,60.579 183.568,92.202 ; 201.972,60.579 201.972,92.202 ; 134.264,60.579 216.362,60.579 216.362,92.202 134.264,92.202 134.264,60.579
  text "Symbol" at 136.162,89.988 h1.83
  text "Quantity" at 143.799,89.988 h1.83
  text "Finished Hole Size" at 152.235,89.988 h1.83
  text "Plated" at 168.402,89.988 h1.83
  text "Hole Type" at 174.986,89.988 h1.83
  text "Drill Layer Pair" at 184.517,89.988 h1.83
  text "Hole Tolerance" at 202.92,89.988 h1.83
  text "2" at 143.799,86.826 h1.52
  text "35.43mil (0.900mm)" at 152.235,86.826 h1.52
  text "NPTH" at 168.402,86.826 h1.52
  text "Round" at 174.986,86.826 h1.52
  text "Top Layer - Bottom Layer" at 184.517,86.826 h1.52
  text "78" at 143.799,83.664 h1.52
  text "11.81mil (0.300mm)" at 152.235,83.664 h1.52
  text "PTH" at 168.402,83.664 h1.52
  text "Round" at 174.986,83.664 h1.52
  text "Top Layer - Bottom Layer" at 184.517,83.664 h1.52
  text "20" at 143.799,80.501 h1.52
  text "15.75mil (0.400mm)" at 152.235,80.501 h1.52
  text "PTH" at 168.402,80.501 h1.52
  text "Round" at 174.986,80.501 h1.52
  text "Top Layer - Bottom Layer" at 184.517,80.501 h1.52
  text "7" at 143.799,77.339 h1.52
  text "19.69mil (0.500mm)" at 152.235,77.339 h1.52
  text "PTH" at 168.402,77.339 h1.52
  text "Round" at 174.986,77.339 h1.52
  text "Top Layer - Bottom Layer" at 184.517,77.339 h1.52
  text "7" at 143.799,74.177 h1.52
  text "33.47mil (0.850mm)" at 152.235,74.177 h1.52
  text "PTH" at 168.402,74.177 h1.52
  text "Round" at 174.986,74.177 h1.52
  text "Top Layer - Bottom Layer" at 184.517,74.177 h1.52
  text "2" at 143.799,71.015 h1.52
  text "50.00mil (1.270mm)" at 152.235,71.015 h1.52
  text "PTH" at 168.402,71.015 h1.52
  text "Round" at 174.986,71.015 h1.52
  text "Top Layer - Bottom Layer" at 184.517,71.015 h1.52
  text "12" at 143.799,67.852 h1.52
  text "63.00mil (1.600mm)" at 152.235,67.852 h1.52
  text "PTH" at 168.402,67.852 h1.52
  text "Round" at 174.986,67.852 h1.52
  text "Top Layer - Bottom Layer" at 184.517,67.852 h1.52
  text "8" at 143.799,64.69 h1.52
  text "122.05mil (3.100mm)" at 152.235,64.69 h1.52
  text "PTH" at 168.402,64.69 h1.52
  text "Round" at 174.986,64.69 h1.52
  text "Top Layer - Bottom Layer" at 184.517,64.69 h1.52
  text "136 Total" at 143.799,61.528 h1.52
  text ".Layer_Name" at 14.656,-21.806 h1.52
M17 Embedded Cavity:
  text ".Layer_Name" at 14.656,-21.806 h1.52
M18 Embedded Assembly:
  text ".Layer_Name" at 14.656,-21.806 h1.52
M19 Embedded Keepout:
  text ".Layer_Name" at 14.656,-21.806 h1.52

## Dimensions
0,-10.16 to 25.4,-10.16 on M2 Board Dimensions
0,66.04 to 73.66,0 on M2 Board Dimensions
73.66,0 to 0,66.04 on M2 Board Dimensions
